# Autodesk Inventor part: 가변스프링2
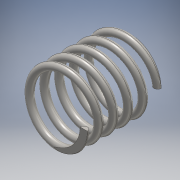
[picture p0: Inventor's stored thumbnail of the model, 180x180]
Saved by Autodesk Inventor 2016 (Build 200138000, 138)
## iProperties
Created: 2019-11
Part Number: 가변스프링2
Material: 스테인레스 스틸
Document SubType Name: Modeling
Designer: user
Density: 8 g/cm^3
Appearance: 반연마
Mass: 6.57569 g
Surface Area: 16.7185 cm^2
Volume: 0.821961 cm^3
Author: user
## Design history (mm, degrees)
sketch "스케치1"
  geometry: L1 (0, 0)-(8.5, 0); L2 (8.5, 0)-(8.5, 20.5); L3 (8.5, 20.5)-(0, 20.5); L4 (0, 20.5)-(0, 0); C1 r 1 at (8.5, 0)
  constraints: 8 end point, 2 parallel, 1 centre point, 1 coincident, 1 horizontal, 1 perpendicular
  dimensions: "d1" = 17 diameter of L2 L4; "d2" = 20.5 distance between parallel lines of L1 L3 (derived); "d3" = 2 diameter of C1
feature "코일1" sketch "스케치1" pitch "d4" = 10; turns "d6" = 5; dims "d5" = 20.5 (= d2), "d7" = 0, angle "d8" = 90 deg, angle "d9" = 90 deg, "d10" = 0, "d11" = 0
sketch "스케치2"
  geometry: L1 (0, 13.879)-(20.5, 13.879); L2 (20.5, 13.879)-(20.5, -13.879); L3 (20.5, -13.879)-(0, -13.879); L4 (0, -13.879)-(0, 13.879); 2 further points
  constraints: 8 end point, 2 parallel, 1 coincident, 1 horizontal, 1 midpoint, 1 perpendicular
  dimensions: "d12" = 20.5 distance between parallel lines of L4 L2 (= d2); "d13" = 27.7574 distance between parallel lines of L1 L3
extrude "돌출1" sketch "스케치2" stored distance "d14" = 50; taper "d15" = 0 deg
node "솔리드1"
